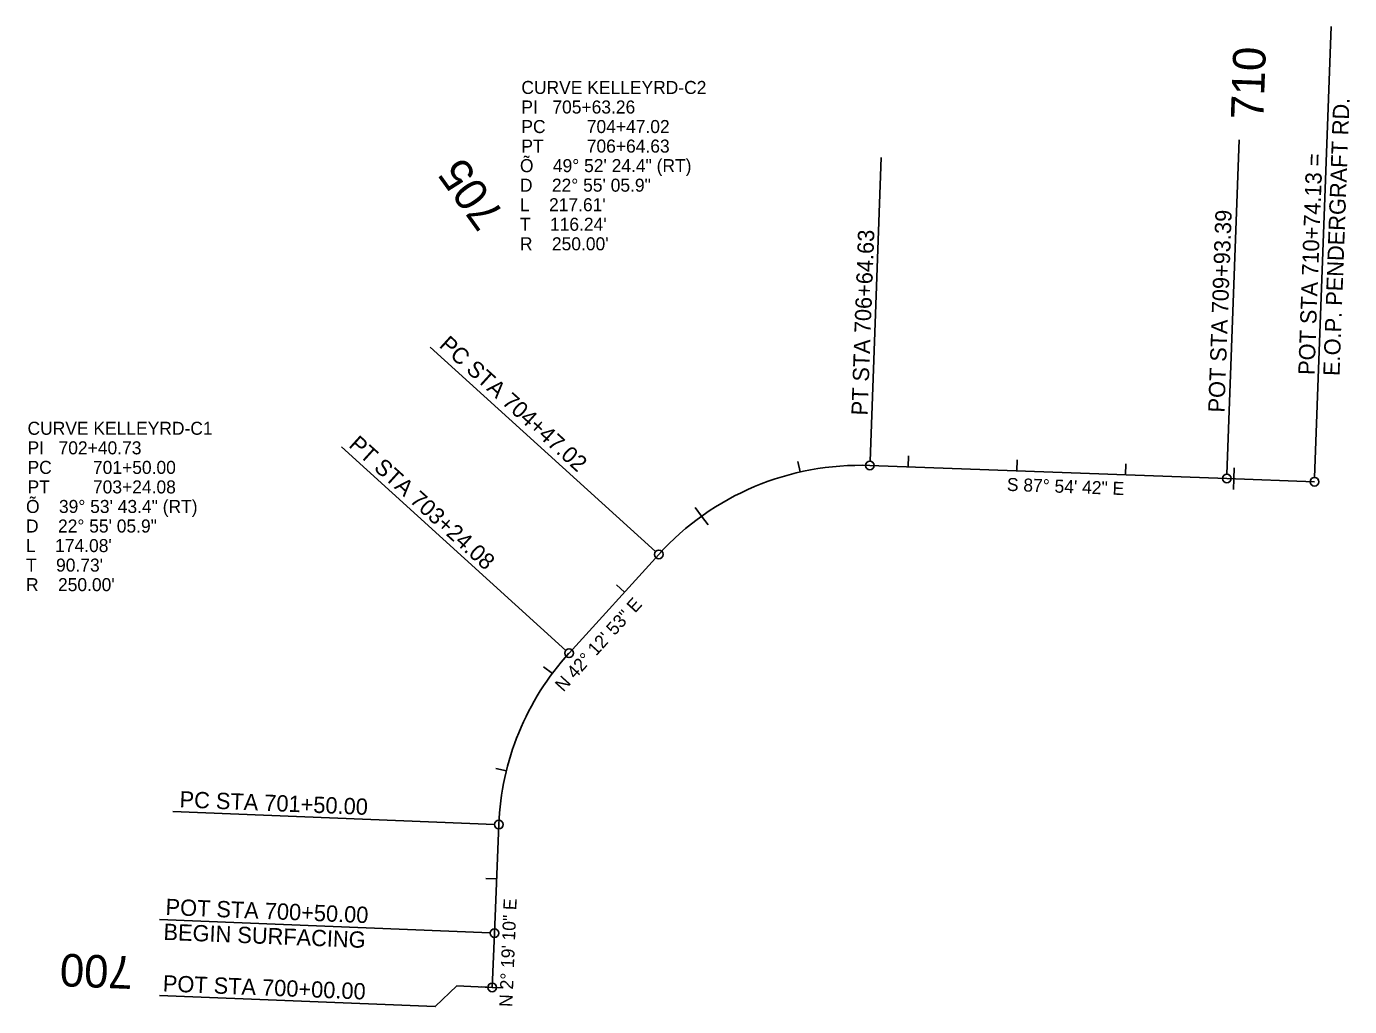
# Model space of a CAD drawing. Extents: x 2819977 to 2827606, y 116785 to 150320.
# Drawn here: x 2825066 to 2826284, y 129358 to 130260 of the extents above; entities that cross this region are included whole.
import ezdxf

# ---------------------------------------------------------------- set-up
doc = ezdxf.new("R2010")
doc.units = 0
for name, color, linetype in [('Modeling-Contours-Minor-Existing', 7, 'Continuous'), ('Modeling-Flow Arrows-Existing', 7, 'Continuous'), ('Modeling-Spot-Existing', 7, 'Continuous'), ('Modeling-Triangle Verticies-Existing', 7, 'Continuous')]:
    doc.layers.add(name, color=color, linetype=linetype)

msp = doc.modelspace()

# ---------------------------------------------------------------- linework, layer by layer
at = {"layer": 'Modeling-Flow Arrows-Existing'}
for p, q in [((2825877.6, 129854.7), (2825877.9, 129864.7)), ((2825778.1, 129850), (2825775.9, 129859.7)), ((2825842.2, 129856), (2826170.8, 129844)), ((2825977.5, 129851), (2825977.9, 129861)), ((2826077.4, 129847.4), (2826077.8, 129857.4)), ((2826177.4, 129843.7), (2826177.7, 129853.7)), ((2826170.8, 129844), (2826251.5, 129841)), ((2826177.4, 129843.7), (2826177, 129833.7)), ((2825687.4, 129809.3), (2825681.6, 129817.4)), ((2825687.4, 129809.3), (2825693.3, 129801.2)), ((2825565.4, 129683.1), (2825648, 129774.1)), ((2825616.4, 129739.3), (2825609, 129746)), ((2825550.1, 129664.5), (2825542, 129670.4)), ((2825507.7, 129574.6), (2825498, 129577)), ((2825496.7, 129425.3), (2825500.7, 129525.2)), ((2825498.7, 129475.2), (2825488.7, 129475.6)), ((2825494.7, 129375.3), (2825496.7, 129425.3)), ((2825494.7, 129375.3), (2825484.7, 129375.7)), ((2825494.7, 129375.3), (2825504.6, 129374.9))]:
    msp.add_line(p, q, dxfattribs=at)
for centre, start, end in [((2825833.1, 129606.1), 87.9117, 137.7851), ((2825750.5, 129515.1), 137.7851, 177.6805)]:
    msp.add_arc(centre, 250, start, end, dxfattribs=at)
at = {"layer": 'Modeling-Spot-Existing'}
for p, q in [((2826251.6, 129845), (2826266.7, 130260.3)), ((2826170.9, 129848), (2826182.1, 130155.8)), ((2825842.4, 129860), (2825852.6, 130139.5)), ((2825645, 129776.8), (2825437.5, 129965)), ((2825562.4, 129685.7), (2825356, 129873)), ((2825496.7, 129525.4), (2825200.8, 129537.3)), ((2825492.7, 129425.4), (2825188.5, 129437.8))]:
    msp.add_line(p, q, dxfattribs=at)
msp.add_lwpolyline([(2825188.3, 129367.9), (2825442.2, 129357.6), (2825462.1, 129376.6), (2825494.7, 129375.3)], dxfattribs=at)
for centre in [(2825842.2, 129856), (2826170.8, 129844), (2826251.5, 129841), (2825648, 129774.1), (2825565.4, 129683.1), (2825500.7, 129525.2), (2825496.7, 129425.3), (2825494.7, 129375.3)]:
    msp.add_circle(centre, 4, dxfattribs=at)

# ---------------------------------------------------------------- texts
at = {"layer": 'Modeling-Contours-Minor-Existing'}
for s, rotation, p in [('S 87%%d 54\' 42" E', 357.9117, (2825968.2, 129832.6)), ('N 42%%d 12\' 53" E', 47.7851, (2825560.2, 129646.8)), ('N 2%%d 19\' 10" E', 87.6805, (2825513.2, 129357.1))]:
    msp.add_text(s, height=12, rotation=rotation, dxfattribs=at).set_placement(p)
at = {"layer": 'Modeling-Flow Arrows-Existing'}
for s, rotation, p in [(' 710', 87.9117, (2826204, 130163)), (' 705', 125.6426, (2825513.2, 130078.1)), (' 700', 177.6805, (2825175.5, 129403.3))]:
    msp.add_text(s, height=30, rotation=rotation, dxfattribs=at).set_placement(p)
at = {"layer": 'Modeling-Spot-Existing'}
for s, rotation, p in [('E.O.P. PENDERGRAFT RD.', 87.9117, (2826274.5, 129938.2)), ('POT STA 710+74.13 =', 87.9117, (2826251.5, 129939.1)), ('POT STA 709+93.39', 87.9117, (2826168.6, 129904.5)), ('PT STA 706+64.63', 87.9117, (2825840.2, 129901.8)), ('PC STA 704+47.02', 317.7851, (2825445, 129965.6)), ('PT STA 703+24.08', 317.7851, (2825361.8, 129873.7)), ('PC STA 701+50.00', 357.6805, (2825206.7, 129541.1)), ('POT STA 700+50.00', 357.6805, (2825193.8, 129442)), ('BEGIN SURFACING', 357.6805, (2825191.9, 129419.1)), ('POT STA 700+00.00', 357.6805, (2825191.3, 129371.6))]:
    msp.add_text(s, height=15, rotation=rotation, dxfattribs=at).set_placement(p)
at = {"layer": 'Modeling-Triangle Verticies-Existing'}
for s, p in [('CURVE KELLEYRD-C2', (2825521.5, 130198.1)), ('PI   705+63.26', (2825521.5, 130180.1)), ('PC', (2825521.5, 130162.1)), ('704+47.02', (2825581.7, 130162.1)), ('PT', (2825521.5, 130144.1)), ('706+64.63', (2825581.7, 130144.1)), ('Õ    49%%d 52\' 24.4" (RT)', (2825520.2, 130126.1)), ('D    22%%d 55\' 05.9"', (2825520.2, 130108.1)), ("L    217.61'", (2825520.2, 130090.1)), ("T    116.24'", (2825520.2, 130072.1)), ("R    250.00'", (2825520.2, 130054.1)), ('CURVE KELLEYRD-C1', (2825067, 129884.2)), ('PI   702+40.73', (2825067, 129866.2)), ('PC', (2825067, 129848.2)), ('701+50.00', (2825127.2, 129848.2)), ('PT', (2825067, 129830.2)), ('703+24.08', (2825127.2, 129830.2)), ('Õ    39%%d 53\' 43.4" (RT)', (2825065.6, 129812.2)), ('D    22%%d 55\' 05.9"', (2825065.6, 129794.2)), ("L    174.08'", (2825065.6, 129776.2)), ("T    90.73'", (2825065.6, 129758.2)), ("R    250.00'", (2825065.6, 129740.2))]:
    msp.add_text(s, height=12, dxfattribs=at).set_placement(p)

doc.saveas('drawing.dxf')
